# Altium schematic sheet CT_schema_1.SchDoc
size 447 x 258 mm
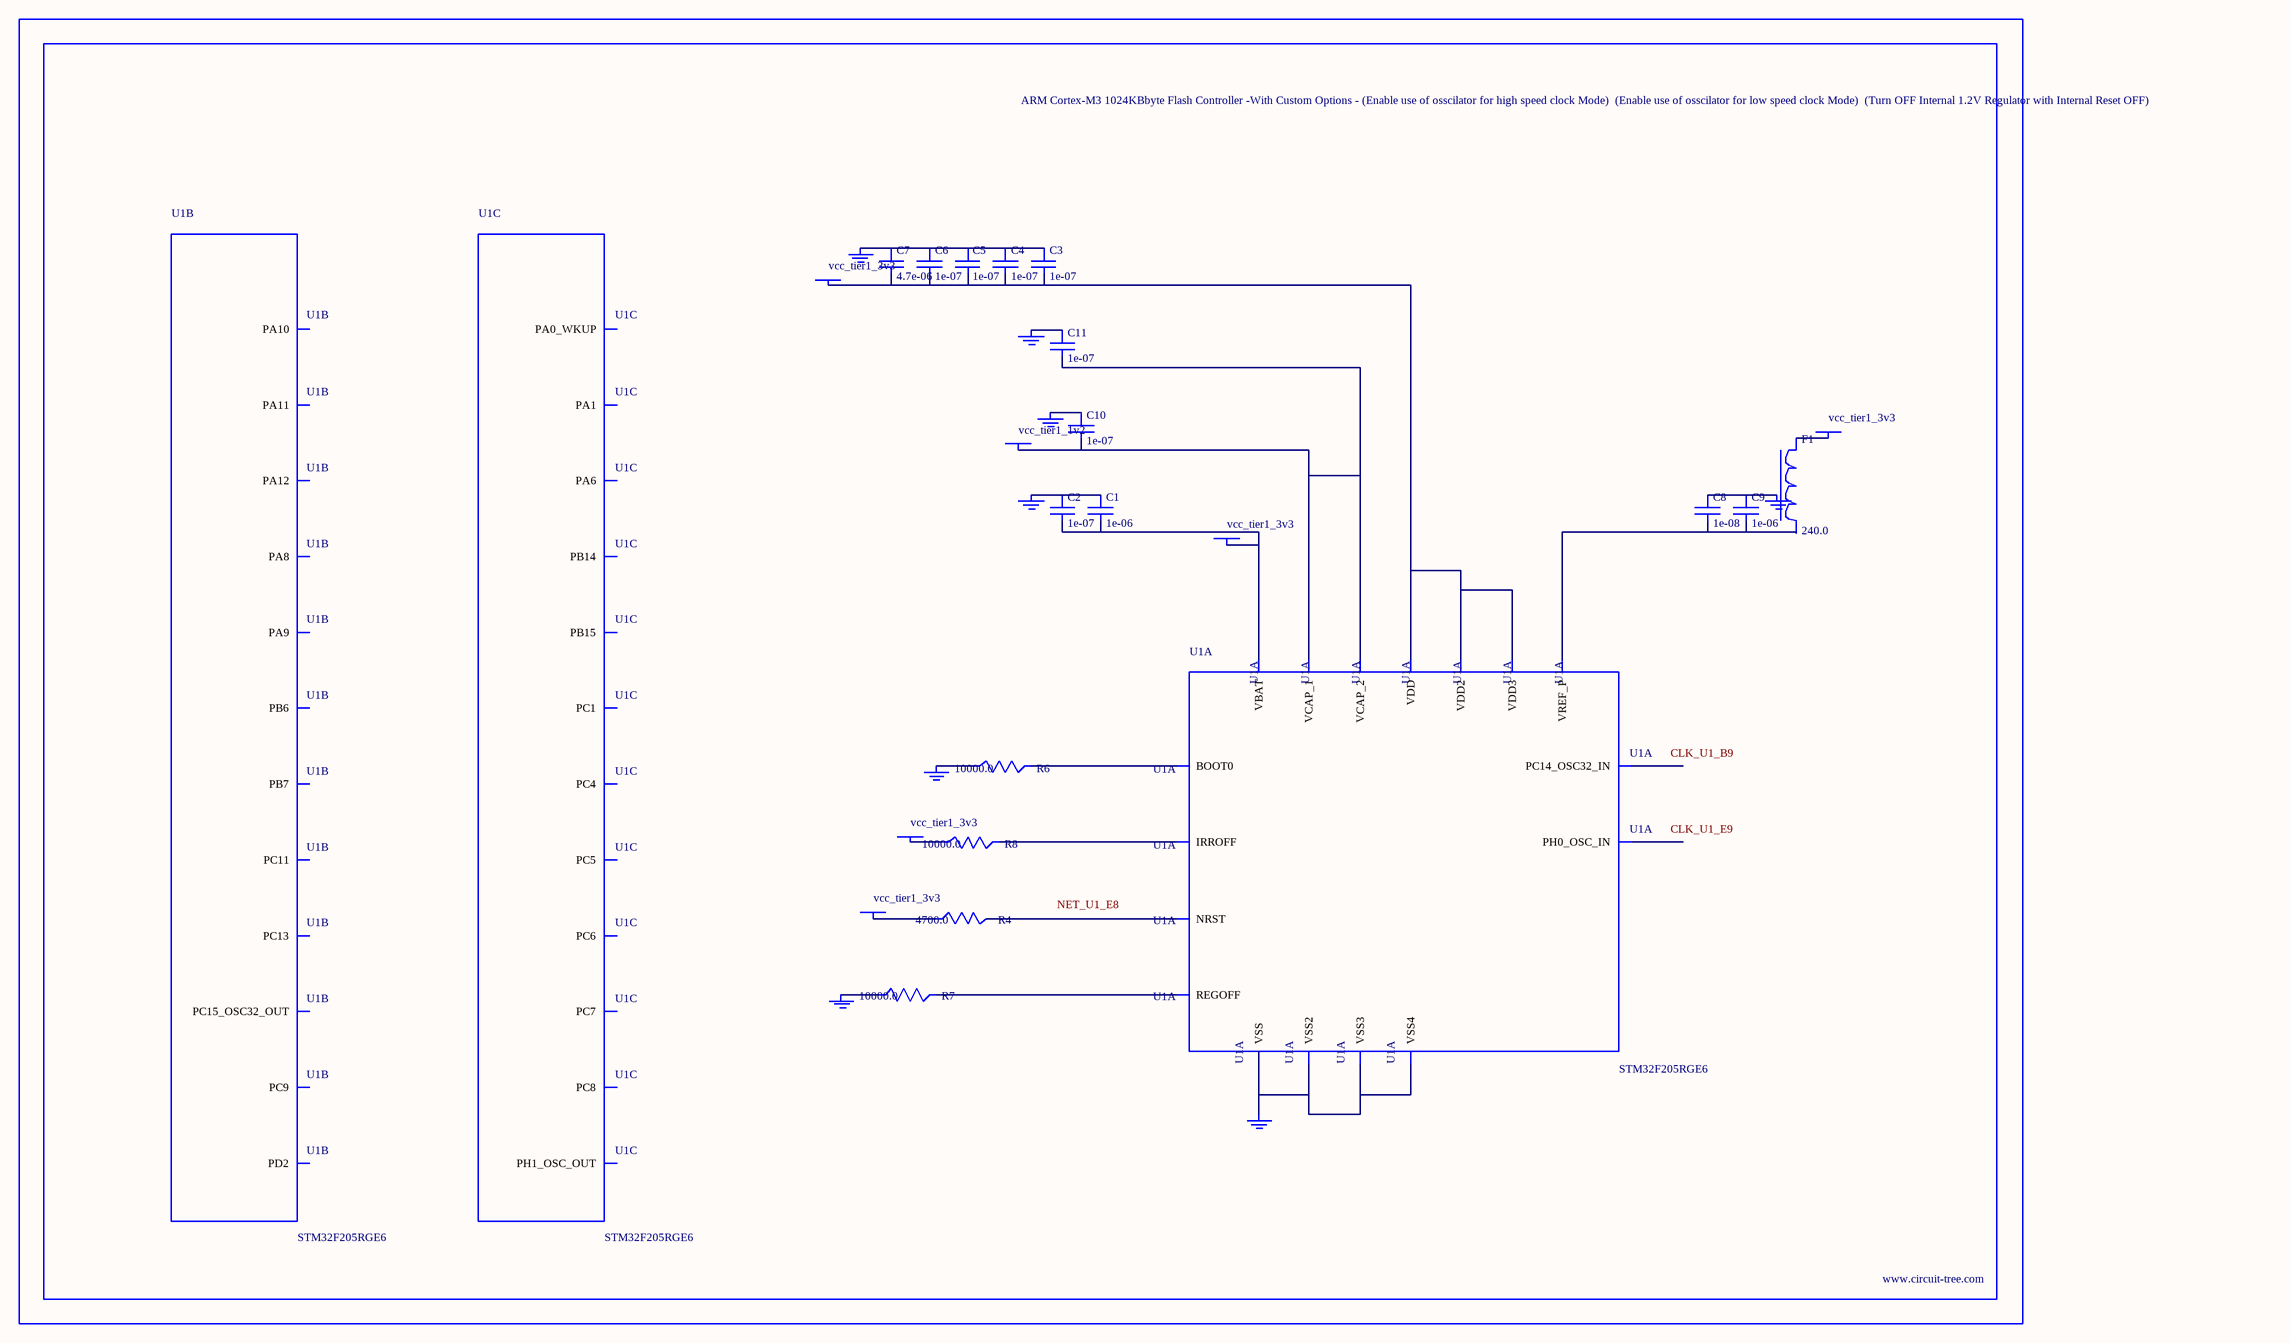
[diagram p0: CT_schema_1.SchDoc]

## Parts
BORDER0  (no value)
C1  1e-06  [C0603]
C2  1e-07  [C0603]
C3  1e-07  [C0603]
C4  1e-07  [C0603]
C5  1e-07  [C0603]
C6  1e-07  [C0603]
C7  4.7e-06  [C0603]
C8  1e-08  [C0603]
C9  1e-06  [C0603]
C10  1e-07  [C0402]
C11  1e-07  [C0402]
F1  240.0  [L0603]
GND_INSTANCE_0_0  (no value)
GND_INSTANCE_0_1  (no value)
GND_INSTANCE_0_2  (no value)
GND_INSTANCE_0_3  (no value)
GND_INSTANCE_0_4  (no value)
GND_INSTANCE_0_5  (no value)
GND_INSTANCE_0_6  (no value)
GND_INSTANCE_0_7  (no value)
POWER_INSTANCE_0_0  vcc_tier1_3v3
POWER_INSTANCE_0_1  vcc_tier1_3v3
POWER_INSTANCE_0_2  vcc_tier1_3v3
POWER_INSTANCE_0_3  vcc_tier1_3v3
POWER_INSTANCE_0_4  vcc_tier1_1v2
POWER_INSTANCE_0_5  vcc_tier1_3v3
R4  4700.0  [R0603]
R6  10000.0  [R0603]
R7  10000.0  [R0603]
R8  10000.0  [R0603]
U1  STM32F205RGE6  [EWLCSP66]  (parts A,B,C of 7)

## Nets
NetC1_1: C1.1 C2.1 GND_INSTANCE_0_0.0(GND)
NetC1_2: C1.2 C2.2 POWER_INSTANCE_0_0.0(PWR) U1.A9(VBAT)
NetC3_1: C3.1 C4.1 C5.1 C6.1 C7.1 GND_INSTANCE_0_1.0(GND)
NetC3_2: C3.2 C4.2 C5.2 C6.2 C7.2 POWER_INSTANCE_0_1.0(PWR) U1.A8(VDD) U1.D9(VDD2) U1.E1(VDD3)
NetC8_1: C8.1 C9.1 GND_INSTANCE_0_3.0(GND)
NetC8_2: C8.2 C9.2 U1.F7(VREF_P)
NetC10_1: C10.1 GND_INSTANCE_0_5.0(GND)
NetC10_2: C10.2 C11.2 POWER_INSTANCE_0_4.0(PWR) U1.C2(VCAP_2) U1.J3(VCAP_1)
NetC11_1: C11.1 GND_INSTANCE_0_6.0(GND)
NetF1_1: F1.1 POWER_INSTANCE_0_2.0(PWR)
NetGND_INSTANCE_0_2_0: GND_INSTANCE_0_2.0(GND) R6.1
NetGND_INSTANCE_0_4_0: GND_INSTANCE_0_4.0(GND) R7.1
NetGND_INSTANCE_0_7_0: GND_INSTANCE_0_7.0(GND) U1.B1(VSS) U1.D8(VSS2) U1.F1(VSS3) U1.H9(VSS4)
NetPOWER_INSTANCE_0_3_0: POWER_INSTANCE_0_3.0(PWR) R8.1
NetPOWER_INSTANCE_0_5_0: POWER_INSTANCE_0_5.0(PWR) R4.1
NetR4_2: R4.2 U1.E8(NRST)
NetR6_2: R6.2 U1.B6(BOOT0)
NetR7_2: R7.2 U1.H7(REGOFF)
NetR8_2: R8.2 U1.C8(IRROFF)

Not connected (* = marked no-connect by the designer): F1 2; U1 A6(PB7) B5(PB6) B8(PC13) B9(PC14_OSC32_IN) C1(PA12) C3(PC11) C7(PD2) C9(PC15_OSC32_OUT) D1(PC9) D2(PA11) D3(PA10) E2(PA8) E3(PA9) E7(PA0_WKUP) E9(PH0_OSC_IN) F2(PC7) F3(PC8) F8(PC1) F9(PH1_OSC_OUT) G1(PB15) G2(PC6) G3(PC5) H1(PB14) H4(PC4) H5(PA6) H8(PA1)

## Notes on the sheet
- Labels drawn without touching a wire or pin: CLK_U1_B9, CLK_U1_E9, NET_U1_E8

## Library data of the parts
BORDER0 = BORDER_PAGE0
C1 C9 = C0603C105K3RACTU
C2-C6 = 06035C104K4Z2A
C7 = GRM188R6YA475KE15D
C8 = 06035C103K4Z2A
C10 C11 = C0402C104K3RACTU
F1 = Z0603C241ASMST
GND_INSTANCE_0_0-GND_INSTANCE_0_7 = GND
POWER_INSTANCE_0_0-POWER_INSTANCE_0_5 = PWR
R4 = RC0603JR-074K7L
R6-R8 = RC0603JR-0710KL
